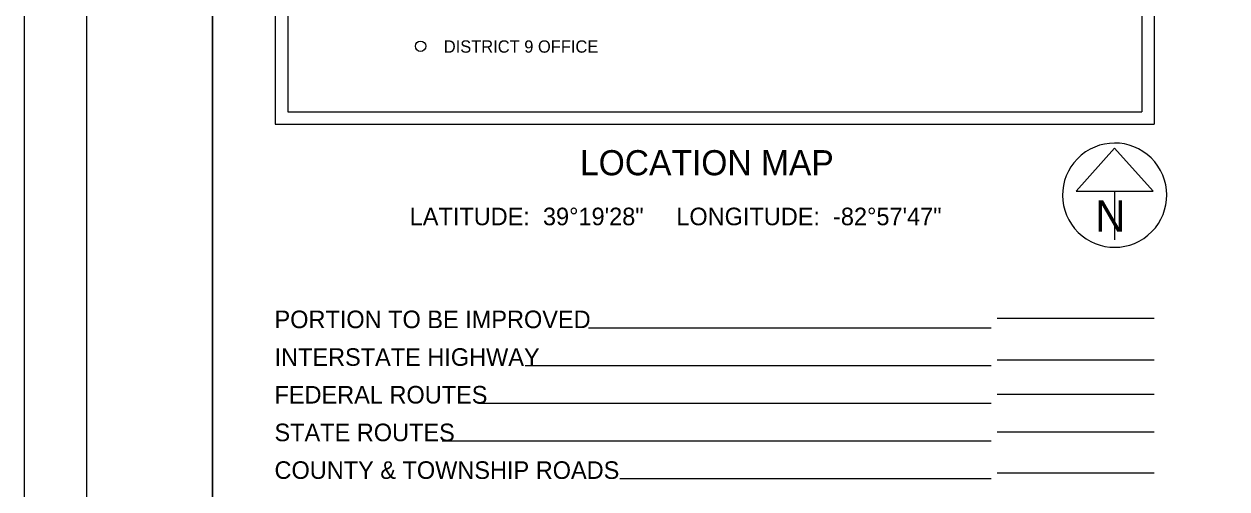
# Model space of a CAD drawing. Extents: x 0 to 34, y 0 to 22.
# Drawn here: x 0 to 9.58, y 11.1 to 14.8 of the extents above; entities that cross this region are included whole.
import ezdxf

# ---------------------------------------------------------------- set-up
doc = ezdxf.new("R2010")
doc.units = 0
for name, color, linetype in [('Default', 7, 'Continuous'), ('SH_Border', 7, 'Continuous'), ('SH_Cut_Line', 7, 'Continuous'), ('SH_Data', 7, 'Continuous'), ('SH_Text', 7, 'Continuous')]:
    doc.layers.add(name, color=color, linetype=linetype)

msp = doc.modelspace()

# ---------------------------------------------------------------- linework, layer by layer
at = {"layer": 'Default'}
msp.add_circle((3.1578, 14.6206), 0.0411, dxfattribs=at)
at = {"layer": 'SH_Border'}
for points in [[(0.5, 21.5), (1.5, 21.5), (1.5, 0.5), (0.5, 0.5)], [(1.5, 21.5), (33.5, 21.5), (33.5, 0.5), (1.5, 0.5)]]:
    msp.add_lwpolyline(points, close=True, dxfattribs=at)
at = {"layer": 'SH_Cut_Line'}
msp.add_lwpolyline([(0, 0), (34, 0), (34, 22), (0, 22)], close=True, dxfattribs=at)
at = {"layer": 'SH_Data'}
for p, q in [((2, 21), (2, 14)), ((9, 21), (9, 14)), ((2.1, 20.9), (2.1, 14.1)), ((8.9, 20.9), (8.9, 14.1)), ((2.1, 14.1), (8.9, 14.1)), ((2.1, 14.1), (2.1, 14.1)), ((2, 14), (9, 14)), ((8.6845, 13.8091), (8.3769, 13.4678)), ((8.9921, 13.4678), (8.6845, 13.8091)), ((8.3769, 13.4678), (8.9921, 13.4678)), ((8.6845, 13.4678), (8.6845, 13.0811)), ((8.6845, 13.4353), (8.6845, 13.4353)), ((8.6845, 13.4353), (8.6845, 13.4353)), ((7.75, 12.4553), (9, 12.4553)), ((7.7, 12.3767), (4.4937, 12.3767)), ((7.7, 12.0767), (3.9895, 12.0767)), ((9, 12.1207), (7.75, 12.1207)), ((9, 11.8491), (7.75, 11.8491)), ((7.7, 11.7767), (3.6192, 11.7767)), ((9, 11.5491), (7.75, 11.5491)), ((7.7, 11.4767), (3.3288, 11.4767)), ((9, 11.2223), (7.75, 11.2223)), ((7.7, 11.1767), (4.7452, 11.1767))]:
    msp.add_line(p, q, dxfattribs=at)
msp.add_arc((8.6845, 13.4353), 0.4148, 129.77984, 129.76332, dxfattribs=at)

# ---------------------------------------------------------------- texts
at = {"layer": 'Default'}
msp.add_text('DISTRICT 9 OFFICE', height=0.098, dxfattribs=at).set_placement((3.3424, 14.5698))
at = {"layer": 'SH_Data'}
msp.add_text('N', height=0.25, dxfattribs=at).set_placement((8.5292, 13.144))
at = {"layer": 'SH_Text'}
for s, height, p in [('LOCATION MAP', 0.2, (4.4269, 13.5938)), ('LATITUDE:  39°19\'28"     LONGITUDE:  -82°57\'47"', 0.14, (3.071, 13.1959)), ('PORTION TO BE IMPROVED', 0.14, (1.9944, 12.3767)), ('INTERSTATE HIGHWAY', 0.14, (1.9944, 12.0767)), ('FEDERAL ROUTES', 0.14, (1.9944, 11.7767)), ('STATE ROUTES', 0.14, (1.9944, 11.4767)), ('COUNTY & TOWNSHIP ROADS', 0.14, (1.9944, 11.1767))]:
    msp.add_text(s, height=height, dxfattribs=at).set_placement(p)

doc.saveas('drawing.dxf')
